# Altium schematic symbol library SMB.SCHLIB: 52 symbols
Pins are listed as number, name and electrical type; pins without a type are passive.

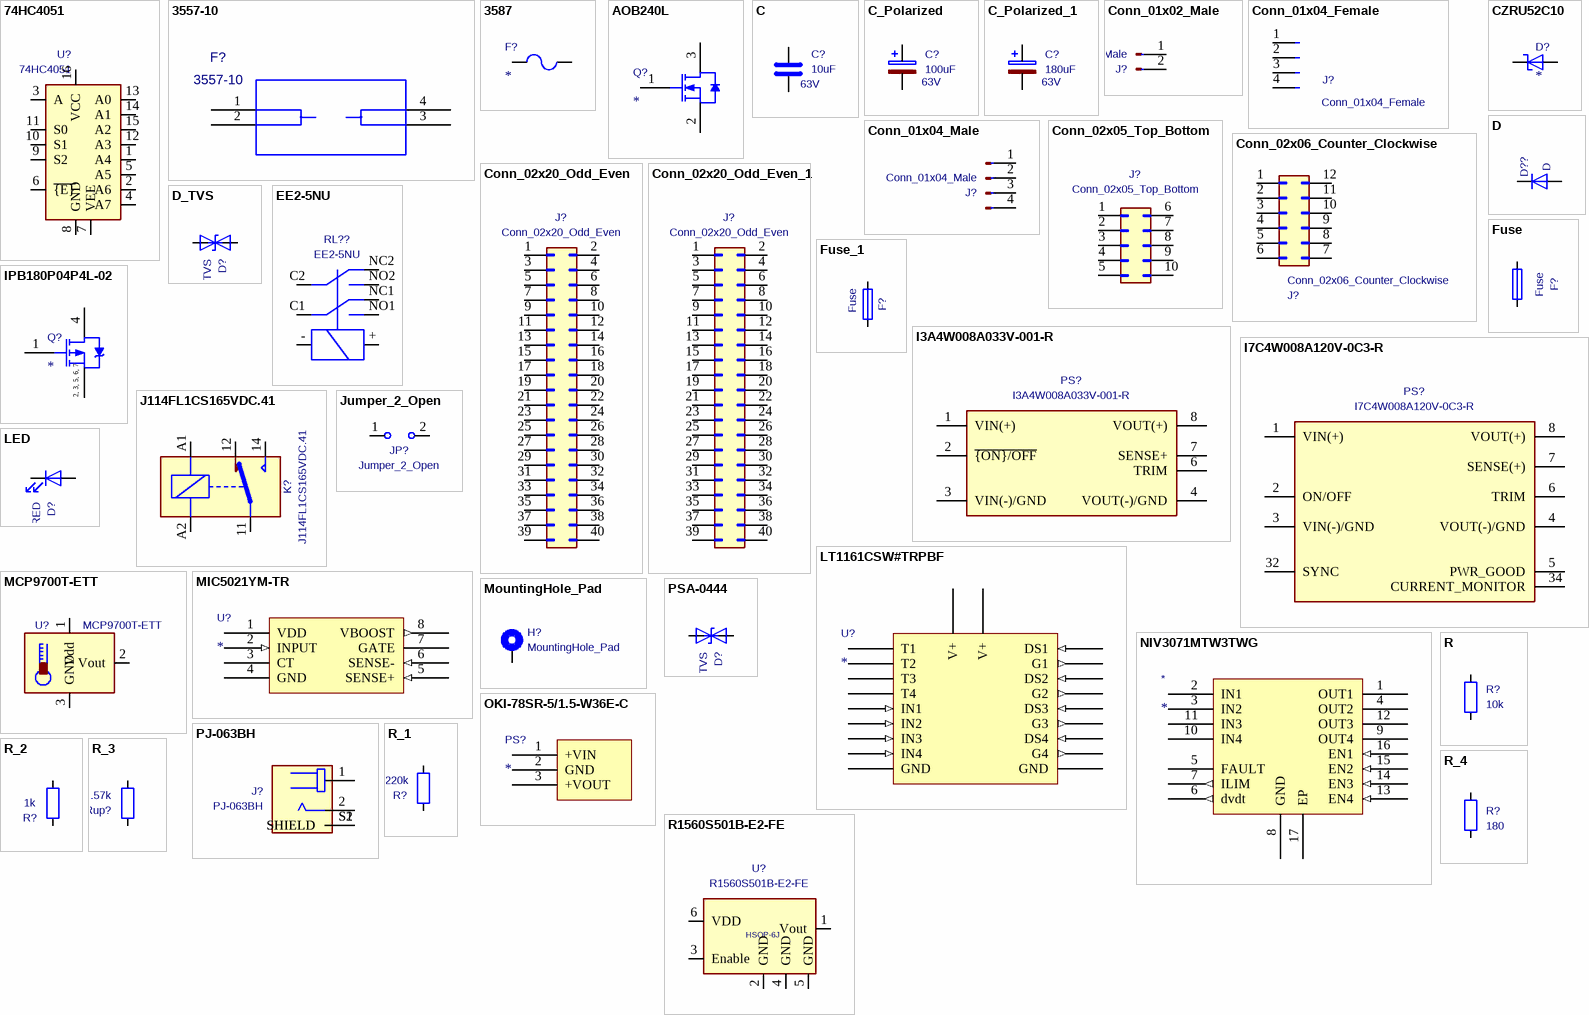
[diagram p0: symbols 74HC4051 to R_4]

## 74HC4051
designator U?
Single-Ended Multiplexer, 1 Func, 8 Channel, CMOS, PDSO16; Manufacturer: Nexperia; Manufacturer Part Number: 74HC4051PW,118; Package Body Material: Plastic; Number of Channels: 8; Channels: 1; Off-state Isolation-Nom: 50dB; On-state Resistance Match-Nom: 9R; On-state Resistance-Max (Ron): 180R; Max Supply Voltage: 10V; Min Supply Voltage: 2V; Nominal Supply Voltage: 5V; Switch-off Time-Max: 87ns; Switch-on Time-Max: 104ns
footprint TSSOP-16_4.4x5mm_P0.65mm
pins: 1 A4, 2 A6, 3 A, 4 A7, 5 A5, 6 ~{{E}}, 7 VEE, 8 GND, 9 S2, 10 S1, 11 S0, 12 A3, 13 A0, 14 A1, 15 A2, 16 VCC

## 3557-10
designator F?
Holder; Fuse; Auto Blade; 30A; PC Pin Terminal; Nylon Holder; Red; Manufacturer: Keystone Electronics
footprint 3557-10
pins: 1, 2, 3, 4

## 3587
designator F?
Fuses/Accessories; Manufacturer: Keystone Electronics; Manufacturer Part Number: 3587
footprint 3587
pins: 1, 2

## AOB240L
designator Q?
Power Field-Effect Transistor, 105A I(D), 1-Element, N-Channel, Metal-oxide Semiconductor FET; Manufacturer: Alpha & Omega Semiconductor; Manufacturer Part Number: AOB240L; Operating Mode: ENHANCEMENT MODE; Power Dissipation-Max (Abs): 176W
footprint TO-263 D2PAK
pins: 1 GATE, 2 SOURCE, 3 DRAIN

## C
designator C?  value 10uF  Voltage: 63V  (hidden comment: C)
Ceramic Capacitor, Multilayer, Ceramic, 63V, 10% +Tol, 10% -Tol, X7R, 15% TC, 10uF, Surface Mount, 1210; Manufacturer: Samsung; Manufacturer Part Number: CL32B106KMVNNWE; Multilayer: Yes
footprint C_1210_3225Metric
pins: 1, 2

## C_Polarized
designator C?  value 100uF  Voltage: 63V  (hidden comment: C_Polarized)
Aluminum Electrolytic Capacitor, Polarized, 63V, 20% +Tol, 20% -Tol, 100uF, Surface Mount, 4141; Manufacturer: KEMET; Manufacturer Part Number: A768MS107M1JLAE027
footprint CP_Elec_10x12.6
pins: 1, 2

## C_Polarized_1
designator C?, comment value 180uF  Voltage: 63V  (hidden comment: Comment)
Cap Alu Hybrid SMD 150C 63V 180F; Manufacturer: KEMET; Manufacturer Part Number: A785MW187M1JLAS013
footprint CP_Elec_10x12.6
pins: 1, 2

## Conn_01x02_Male
designator J?
Barrier Strip Terminal Block, 8A, 1 Row(s), 1 Deck(s); Manufacturer: Phoenix Contact; Manufacturer Part Number: 1843606; Fastening Method: CONNECTOR; Number of Decks: 1; Number of Ways: 2; Voltage Rating: 160V; Safety Approval: UL
footprint 1843606
pins: 1 Pin_1, 2 Pin_2

## Conn_01x04_Female
designator J?
Board Connector, 4 Contact(s), 1 Row(s), Female, Straight, 0.1 inch Pitch, Solder Terminal, Locking; Manufacturer: Sullins; Manufacturer Part Number: PPPC041LFBN-RC; Manufacturer Series: PP; Contact Pattern: RECTANGULAR; Contact Style: SQ PIN-SKT; Number Of Connectors: 1; Polarization Key: POLARIZED HOUSING; Rated Current (Signal): 3A; Number of Contacts: 4; Body Breadth: 0.094inch; Body Depth: 0.334inch; Body Length: 0.42inch; Reference Standard: UL; Reliability: COMMERCIAL
footprint PinHeader_1x04_P2.54mm_Vertical
pins: 1 Pin_1, 2 Pin_2, 3 Pin_3, 4 Pin_4

## Conn_01x04_Male
designator J?
Strip Terminal Block, 16A, 1 Row(s), 1 Deck(s); Manufacturer: Phoenix Contact; Manufacturer Part Number: 1924321; Fastening Method: CONNECTOR; Number of Decks: 1; Number of Ways: 4; Voltage Rating: 320V; Safety Approval: UL,VDE,CUL,CB,EAC
footprint 1924321
pins: 1 Pin_1, 2 Pin_2, 3 Pin_3, 4 Pin_4

## Conn_02x05_Top_Bottom
designator J?
Board Connector, 10 Contact(s), 2 Row(s), Female, Straight, 0.1 inch Pitch, Solder Terminal, Locking; Manufacturer: Sullins; Manufacturer Part Number: PPPC052LFBN-RC; Manufacturer Series: PP; Option: General Purpose; Contact Pattern: RECTANGULAR; Contact Style: SQ PIN-SKT; Filter Feature: No; Number Of Connectors: 1; Number Of PCB Rows: 2; Polarization Key: POLARIZED HOUSING; Rated Current (Signal): 3A; Number of Contacts: 10; Body Breadth: 0.197inch; Body Depth: 0.334inch; Body Length: 0.52inch; PCB Contact Row Spacing: 2.54mm; Reference Standard: UL; Reliability: COMMERCIAL
footprint PinSocket_2x05_P2.54mm_Vertical
pins: 1 Pin_1, 2 Pin_2, 3 Pin_3, 4 Pin_4, 5 Pin_5, 6 Pin_6, 7 Pin_7, 8 Pin_8, 9 Pin_9, 10 Pin_10

## Conn_02x06_Counter_Clockwise
designator J?
Board Connector, 12 Contact(s), 2 Row(s), Female, Straight, 0.1 inch Pitch, Solder Terminal, Locking; Manufacturer: Sullins; Manufacturer Part Number: PPPC062LFBN-RC; Manufacturer Series: PP; Contact Pattern: RECTANGULAR; Contact Style: SQ PIN-SKT; Number Of Connectors: 1; Number Of PCB Rows: 2; Polarization Key: POLARIZED HOUSING; Rated Current (Signal): 3A; Number of Contacts: 12; Body Breadth: 0.197inch; Body Depth: 0.334inch; Body Length: 0.62inch; PCB Contact Row Spacing: 2.54mm; Reference Standard: UL; Reliability: COMMERCIAL
footprint PinHeader_2x06_P2.54mm_Vertical
pins: 1 Pin_1, 2 Pin_2, 3 Pin_3, 4 Pin_4, 5 Pin_5, 6 Pin_6, 7 Pin_7, 8 Pin_8, 9 Pin_9, 10 Pin_10, 11 Pin_11, 12 Pin_12

## Conn_02x20_Odd_Even
designator J?
Board Connector; Manufacturer: Omron; Manufacturer Part Number: XG4A-4035; Manufacturer Series: XG4A
footprint PinHeader_2x20_P2.54mm_Horizontal
pins: 1 Pin_1, 2 Pin_2, 3 Pin_3, 4 Pin_4, 5 Pin_5, 6 Pin_6, 7 Pin_7, 8 Pin_8, 9 Pin_9, 10 Pin_10, 11 Pin_11, 12 Pin_12, 13 Pin_13, 14 Pin_14, 15 Pin_15, 16 Pin_16, 17 Pin_17, 18 Pin_18, 19 Pin_19, 20 Pin_20, 21 Pin_21, 22 Pin_22, 23 Pin_23, 24 Pin_24, 25 Pin_25, 26 Pin_26, 27 Pin_27, 28 Pin_28, 29 Pin_29, 30 Pin_30, 31 Pin_31, 32 Pin_32, 33 Pin_33, 34 Pin_34, 35 Pin_35, 36 Pin_36, 37 Pin_37, 38 Pin_38, 39 Pin_39, 40 Pin_40

## Conn_02x20_Odd_Even_1
designator J?, comment Conn_02x20_Odd_Even
Board Connector, 40 Contact(s), 2 Row(s), Female, Straight, 0.1 inch Pitch, Solder Terminal, Locking; Manufacturer: Sullins; Manufacturer Part Number: PPPC202LFBN-RC; Manufacturer Series: PP; Contact Pattern: RECTANGULAR; Contact Style: SQ PIN-SKT; Number Of Connectors: 1; Number Of PCB Rows: 2; Polarization Key: POLARIZED HOUSING; Rated Current (Signal): 3A; Number of Contacts: 40; Body Breadth: 0.197inch; Body Depth: 0.334inch; Body Length: 2.02inch; PCB Contact Row Spacing: 2.54mm; Reference Standard: UL; Reliability: COMMERCIAL
footprint PinHeader_2x20_P2.54mm_Vertical
pins: 1 Pin_1, 2 Pin_2, 3 Pin_3, 4 Pin_4, 5 Pin_5, 6 Pin_6, 7 Pin_7, 8 Pin_8, 9 Pin_9, 10 Pin_10, 11 Pin_11, 12 Pin_12, 13 Pin_13, 14 Pin_14, 15 Pin_15, 16 Pin_16, 17 Pin_17, 18 Pin_18, 19 Pin_19, 20 Pin_20, 21 Pin_21, 22 Pin_22, 23 Pin_23, 24 Pin_24, 25 Pin_25, 26 Pin_26, 27 Pin_27, 28 Pin_28, 29 Pin_29, 30 Pin_30, 31 Pin_31, 32 Pin_32, 33 Pin_33, 34 Pin_34, 35 Pin_35, 36 Pin_36, 37 Pin_37, 38 Pin_38, 39 Pin_39, 40 Pin_40

## CZRU52C10
designator D?
Zener Diode, 10V V(Z), 5%, 0.15W, Silicon, Unidirectional; Manufacturer: Comchip; Manufacturer Part Number: CZRU52C10; Package Body Material: Plastic; Number of Elements: 1; Max Power Dissipation: 150mW; Test Current: 5mA; Time @ Peak Reflow Temperature-Max (s): 30s
pins: 1 K, 2 A

## D
designator D??, comment value D  (hidden comment: Comment)
Rectifier Diode, Schottky, 1 Phase, 1 Element, 1A, 40V V(RRM), Silicon; Manufacturer: MCC; Manufacturer Part Number: SM5819PL-TP; Package Body Material: Plastic; Non-rep Pk Forward Current-Max: 30A; Number of Elements: 1; Max Power Dissipation: 1.14W; Time @ Peak Reflow Temperature-Max (s): 10s; Qualification Status: Not Qualified
footprint D_SOD-123F
pins: 1 K, 2 A

## D_TVS
designator D?
Trans Voltage Suppressor Diode, 400W, 51V V(RWM), Bidirectional, 1 Element, Silicon, DO-214AC; Manufacturer: Littelfuse; Manufacturer Part Number: SMAJ51CA; Package Body Material: Plastic; Max Breakdown Voltage: 62.7V; Min Breakdown Voltage: 56.7V; Breakdown Voltage-Nom: 59.7V; Clamping Voltage-Max: 82.4V; Number of Elements: 1; Time @ Peak Reflow Temperature-Max (s): 40s; Qualification Status: Not Qualified
footprint D_SMA
pins: 1 A1, 2 A2

## EE2-5NU
designator RL??, comment value EE2-5NU  (hidden comment: Comment)
Power/Signal Relay; Manufacturer: KEMET; Manufacturer Part Number: EE2-5NU-L
footprint EE2-5NU
pins: +, -, C1, C2, NC1, NC2, NO1, NO2

## Fuse
designator F?
Fuse Chip Medium Time Delay Acting 25A 250V SMD Solder Pad 3912 9.8 X 3.05 X 4.06mm Ceramic; Manufacturer: Bel; Manufacturer Part Number: 0678L9250-02; Fuse Type: Board Mount (Cartridge Style Excluded); Voltage Rating (DC): 72V; DC Cold Resistance: 1.9mR
footprint FUSC9830X318N
pins: 1, 2

## Fuse_1
designator F?, comment value Fuse  (hidden comment: Comment)
footprint Fuse_1206_3216Metric_Pad1.42x1.75mm_HandSolder
pins: 1, 2

## I3A4W008A033V-001-R
designator PS?
DC-DC Regulated Power Supply Module, 1 Output, 100W, Hybrid; MANUFACTURER: TDK-Lambda
footprint CONV_I3A4W008A033V-001-R
pins: 1 VIN(+), 2 ~{{ON}/OFF}, 3 VIN(-)/GND, 4 VOUT(-)/GND, 6 TRIM, 7 SENSE+, 8 VOUT(+)

## I7C4W008A120V-0C3-R
designator PS?
Power Supply Module; MANUFACTURER: TDK; SNAPEDA_PN: i7C4W012A050V-0C3-R
footprint CONV_I7C4W008A120V-0C3-R
pins: 1 VIN(+), 2 ON/OFF, 3 VIN(-)/GND, 4 VOUT(-)/GND, 5 PWR_GOOD, 6 TRIM, 7 SENSE(+), 8 VOUT(+), 32 SYNC, 34 CURRENT_MONITOR

## IPB180P04P4L-02
designator Q?
Power Field-Effect Transistor, 180A I(D), 40V, 0.0039ohm, 1-Element, P-Channel, Silicon, Metal-oxide Semiconductor FET, TO-263; Manufacturer: Infineon; Manufacturer Part Number: IPB180P04P4L-02; Package Body Material: Plastic; Avalanche Energy Rating (Eas): 84mJ; Case Connection: DRAIN; Drain-source On Resistance-Max: 3.9mR; Number of Elements: 1; Operating Mode: ENHANCEMENT MODE; Pulsed Drain Current-Max (IDM): 720A; Transistor Application: SWITCHING; Power Dissipation-Max (Abs): 150W
pins: 1 GATE, 2 SOURCE, 3 SOURCE, 3 SOURCE, 4 DRAIN, 4 SOURCE, 5 SOURCE, 6 SOURCE, 7 SOURCE

## J114FL1CS165VDC.41
designator K?
Relay Ul Approved Gen Purpose Sp; Manufacturer: CIT Relay & Switch
footprint Big Pads - Relay_SPDT_Schrack-RT1-16A-FormC_RM5mm
pins: 11, 12, 14, A1, A2

## Jumper_2_Open
designator JP?, comment value Jumper_2_Open  (hidden comment: Comment)
footprint PinHeader_1x02_P2.54mm_Vertical
pins: 1 A, 2 B

## LED
designator D?  value RED  (hidden comment: LED)
Single Color LED, Red, Water Clear, 2.06mm; Manufacturer: Vishay Lite-On; Manufacturer Part Number: LTST-C150KRKT; Shape: Rectangular; Forward Current: 30mA; Forward Voltage: 2.4V; Luminous Intensity-Min: 130cd; Luminous Intensity-Nom: 54mcd; Channels: 1; Reverse Voltage-Max: 5V; Viewing Angle: 130°; Overall Height: 1.1mm
footprint LED_1206_3216Metric
pins: 1 K, 2 A

## LT1161CSW#TRPBF
designator U?
Buffer/Inverter Based MOSFET Driver, PDSO20; Manufacturer: Analog Devices / Linear Technology; Manufacturer Part Number: LT1161CSW#TRPBF; Package Body Material: Plastic; High Side Driver: Yes; Interface IC Type: BUFFER OR INVERTER BASED MOSFET DRIVER; Channels: 4; Max Supply Voltage: 48V; Min Supply Voltage: 12V; Nominal Supply Voltage: 24V; Time @ Peak Reflow Temperature-Max (s): 30s; Turn-Off Delay Time: 200us; Turn-On Delay Time: 400us; Qualification Status: Not Qualified
footprint 20-SOIC
pins: 1 GND, 2 T1, 3 IN1 (in), 4 T2, 5 IN2 (in), 6 T3, 7 IN3 (in), 8 T4, 9 IN4 (in), 10 GND (power), 11 V+, 12 G4 (out), 13 DS4 (in), 14 G3 (out), 15 DS3 (in), 16 G2 (out), 17 DS2 (in), 18 G1 (out), 19 DS1 (in), 20 V+

## MCP9700T-ETT
designator U?
Analog Voltage Output Sensor, 12 Bit(s), 6Cel, Rectangular, 3 Pin, Surface Mount; Manufacturer: Microchip; Manufacturer Part Number: MCP9700T-E/TT; Package Body Material: Plastic; Accuracy-Max (Cel): 4°C; Linearity (Cel): 0.5°C; Operating Current-Max: 12uA; Package Equivalence Code: TO-236; Power Supplies: 2.5/5V; Sensor Type: TEMPERATURE SENSOR,ANALOG,VOLTAGE OUTPUT; Max Supply Voltage: 5.5V; Min Supply Voltage: 2.3V; Body Breadth: 1.3mm; Body Height: 1.01mm; Body Length or Diameter: 2.9mm
footprint SOT-23
pins: 1 Vdd, 2 Vout, 3 GND

## MIC5021YM-TR
designator U?
Buffer/Inverter Based MOSFET Driver, PDSO8; Manufacturer: Microchip; Manufacturer Part Number: MIC5021YM-TR; Package Body Material: Plastic; High Side Driver: Yes; Interface IC Type: BUFFER OR INVERTER BASED MOSFET DRIVER; Channels: 1; Max Supply Voltage: 36V; Min Supply Voltage: 12V; Time @ Peak Reflow Temperature-Max (s): 40s; Turn-Off Delay Time: 1.5us; Turn-On Delay Time: 1us; Qualification Status: Not Qualified
footprint 8-SOIC
pins: 1 VDD (power), 2 INPUT (in), 3 CT (power), 4 GND (power), 5 SENSE+ (in), 6 SENSE- (in), 7 GATE (power), 8 VBOOST (out)

## MountingHole_Pad
designator H?, comment value MountingHole_Pad  (hidden comment: Comment)
footprint MountingHole_3.2mm_M3_DIN965_Pad
pins: 1

## NIV3071MTW3TWG
designator *
Electronic fuse (eFuse) 4-channel, 8V to 60V, 10A in 5x6mm package Latch version; Manufacturer: onsemi; Manufacturer Part Number: NIV3071MTW3TWG
footprint 16-WQFN-5x6
pins: 1 OUT1 (power), 2 IN1 (power), 3 IN2 (power), 4 OUT2 (power), 5 FAULT (oc), 6 dvdt (out), 7 ILIM (out), 8 GND, 9 OUT4 (power), 10 IN4 (power), 11 IN3 (power), 12 OUT3 (power), 13 EN4 (in), 14 EN3 (in), 15 EN2 (in), 16 EN1 (in), 17 EP

## OKI-78SR-5/1.5-W36E-C
designator PS?
DC-DC Regulated Power Supply Module, 1 Output, 7.8W, Hybrid; Manufacturer: Murata; Manufacturer Part Number: OKI-78SR-5/1.5-W36E-C; Max Supply Voltage: 36V; Min Input Voltage: 7V; Nominal Supply Voltage: 12V; Load Regulation-Max: 0.4%; Channels: 1; Max Output Voltage: 5.2V; Min Output Voltage: 4.8V; Nominal Output Voltage: 5V; Surface Mount: No; Trim/Adjustable Output: No
footprint OKI-78SR-5&slash_1.5-W36E-C
pins: 1 +VIN (power), 2 GND (power), 3 +VOUT (power)

## PJ-063BH
designator J?
Circular DC Power Connector, 24V, 8A, 2.5mm Dia; MANUFACTURER: CUI INC
footprint CUI_PJ-063BH
pins: 1, 2, S1 SHIELD, S2 SHIELD

## PSA-0444
designator D?, comment value D_TVS  (hidden comment: Comment)
Trans Voltage Suppressor Diode, 400W, 51V V(RWM), Bidirectional, 1 Element, Silicon, DO-214AC; Manufacturer: Littelfuse; Manufacturer Part Number: SMAJ51CA; Package Body Material: Plastic; Max Breakdown Voltage: 62.7V; Min Breakdown Voltage: 56.7V; Breakdown Voltage-Nom: 59.7V; Clamping Voltage-Max: 82.4V; Number of Elements: 1; Time @ Peak Reflow Temperature-Max (s): 40s; Qualification Status: Not Qualified
footprint D_SMA
pins: 1 A1, 2 A2

## R
designator R?  value 10k  (hidden comment: R)
Fixed Resistor, Thin Film, 0.25W, 10000ohm, 200V, 1% +/-Tol, 50ppm/Cel, Surface Mount, 1206; Manufacturer: Yageo; Manufacturer Part Number: RT1206FRE0710KL; Additional Feature: HIGH PRECISION; Rated Temperature: 70°C; Temperature Coefficient (ppm/Cel): 50; Package Height: 0.55mm; Package Length: 3.1mm; Package Width: 1.6mm; Power: 250mW
footprint R_1206_3216Metric
pins: 1, 2

## R1560S501B-E2-FE
designator U?, comment value R1560S501B-E2-FE  (hidden comment: Comment)
test
footprint HSOP-6J
pins: 1 Vout, 2 GND, 3 Enable, 4 GND, 5 GND, 6 VDD

## R_1
designator R?, comment value 220k  (hidden comment: Comment)
footprint R_1206_3216Metric
pins: 1, 2

## R_2
designator R?, comment value 1k  (hidden comment: Comment)
footprint R_1206_3216Metric
pins: 1, 2

## R_3
designator Rup?, comment value 7.57k  (hidden comment: Comment)
footprint R_1206_3216Metric
pins: 1, 2

## R_4
designator R?  value 180  (hidden comment: R_4)
Fixed Resistor, Metal Glaze/thick Film, 4W, 180ohm, 250V, 5% +/-Tol, 100ppm/Cel, Surface Mount, 2817; Manufacturer: TE Connectivity; Manufacturer Part Number: 3540180RJT
footprint RES_3540_TEC
pins: 1, 2

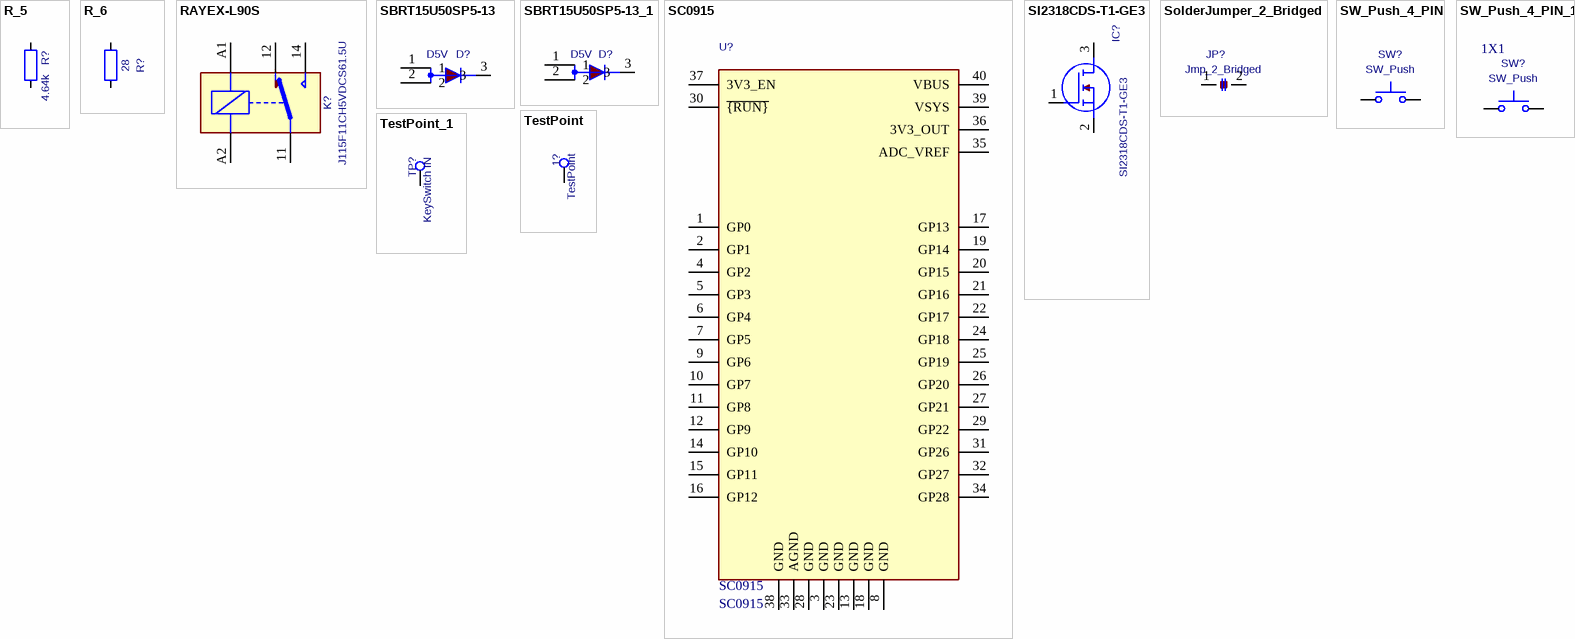
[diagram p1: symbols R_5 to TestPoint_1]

## R_5
designator R?, comment value 4.64k  (hidden comment: Comment)
footprint R_1206_3216Metric
pins: 1, 2

## R_6
designator R?, comment value 28  (hidden comment: PSA-0033)
Fixed Resistor, Metal Glaze/thick Film, 0.25W, 28ohm, 200V, 1% +/-Tol, 100ppm/Cel, Surface Mount, 1206; Manufacturer: Stackpole Electronics; Manufacturer Part Number: RMCF1206FT28R0; Power: 250mW; Rated Temperature: 70°C; Temperature Coefficient (ppm/Cel): 100; Package Height: 0.55mm; Package Length: 3.2mm; Package Width: 1.6mm; Reference Standard: AEC-Q200
footprint R_1206_3216Metric
pins: 1, 2

## RAYEX-L90S
designator K?, comment value J115F11CH5VDCS61.5U  (hidden comment: Comment)
footprint Relay_SPDT_RAYEX-L90S
pins: 11, 12, 14, A1, A2

## SBRT15U50SP5-13
designator D?, comment value D5V  (hidden comment: Comment)
footprint POWERDI5_DIO
pins: 1, 2, 3

## SBRT15U50SP5-13_1
designator D?, comment value D5V  (hidden comment: Comment)
footprint POWERDI5_DIO
pins: 1, 2, 3

## SC0915
designator U?
Raspberry Pi Pico Embedded Dev Module ¦ Raspberry Pi SC0915
footprint MODULE_SCO915_Custom_HeaderStyle
pins: 1 GP0, 2 GP1, 3 GND, 4 GP2, 5 GP3, 6 GP4, 7 GP5, 8 GND, 9 GP6, 10 GP7, 11 GP8, 12 GP9, 13 GND, 14 GP10, 15 GP11, 16 GP12, 17 GP13, 18 GND, 19 GP14, 20 GP15, 21 GP16, 22 GP17, 23 GND, 24 GP18, 25 GP19, 26 GP20, 27 GP21, 28 GND, 29 GP22, 30 ~{{RUN}}, 31 GP26, 32 GP27, 33 AGND, 34 GP28, 35 ADC_VREF, 36 3V3_OUT, 37 3V3_EN, 38 GND, 39 VSYS, 40 VBUS

## SI2318CDS-T1-GE3
designator IC?
Small Signal Field-Effect Transistor, 5.6A I(D), 40V, 1-Element, N-Channel, Silicon, Metal-oxide Semiconductor FET, TO-236AB; MANUFACTURER_NAME: Vishay; Manufacturer: Vishay Siliconix; Package Body Material: Plastic; Drain-source On Resistance-Max: 42mR; Number of Elements: 1; Operating Mode: ENHANCEMENT MODE; Power Dissipation-Max (Abs): 2.1W; Time @ Peak Reflow Temperature-Max (s): 30s; Transistor Application: SWITCHING; Qualification Status: Not Qualified
footprint SOT95P237X112-3N
pins: 1, 2, 3

## SolderJumper_2_Bridged
designator JP?, comment value Jmp_2_Bridged  (hidden comment: Comment)
footprint SolderJumper-2_P1.3mm_Bridged_Pad1.0x1.5mm
pins: 1 A, 2 B

## SW_Push_4_PIN
designator SW?  value SW_Push  (hidden comment: SW_Push_4_PIN)
Keypad Switch, 1 Switches, SPST, Momentary, 0.05A, 12VDC, 3.04N, Solder Terminal, Surface Mount-straight; Manufacturer: E-Switch; Manufacturer Part Number: TL3305BF260QG; Circuit Configuration: 1X1; Contact Current(DC)-Max: 50mA; Contact DC Max Rating R Load: .05A@12VDC; Contact Voltage(DC)-Max: 12V; Number of Switches: 1; Body Breadth: 4.5mm; Body Height: 4.9mm
footprint SW_TL3305BF260QG
pins: 1, 2

## SW_Push_4_PIN_1
designator SW?, comment value SW_Push  Type: 1X1  (hidden comment: PSA-0047)
Keypad Switch, 1 Switches, SPST, Momentary, 0.05A, 12VDC, 3.04N, Solder Terminal, Surface Mount-straight; Manufacturer: E-Switch; Manufacturer Part Number: TL3305BF260QG; Contact Current(DC)-Max: 50mA; Contact DC Max Rating R Load: .05A@12VDC; Contact Voltage(DC)-Max: 12V; Number of Switches: 1; Body Breadth: 4.5mm; Body Height: 4.9mm
footprint SW_TL3305BF260QG
pins: 1, 2

## TestPoint
designator 1?, comment value TestPoint  (hidden comment: Comment)
footprint TestPoint_Pad_D1.0mm
pins: 1

## TestPoint_1
designator TP?, comment value KeySwitch IN  (hidden comment: Comment)
footprint TestPoint_Pad_D1.0mm
pins: 1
